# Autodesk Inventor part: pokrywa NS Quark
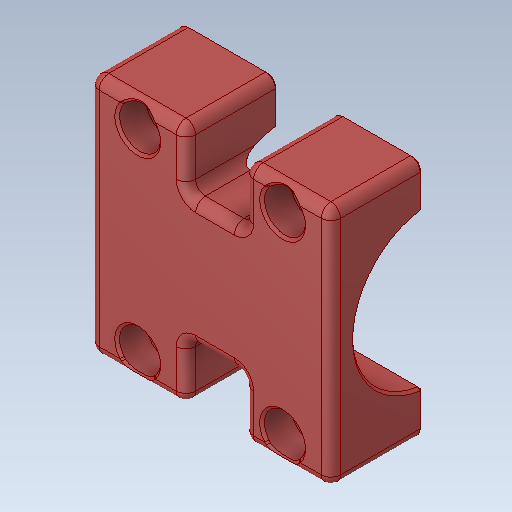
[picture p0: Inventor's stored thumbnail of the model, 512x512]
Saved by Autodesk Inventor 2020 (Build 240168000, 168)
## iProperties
Created: 2015-11
Part Number: pokrywa NS Quark
Material: Ogólny
Document SubType Name: Modeling
Designer: Tomasz
Density: 1 g/cm^3
Appearance: Domyślna
Sending System: SolidWorks 2017
Last Author: Tomasz
Last Saved: 2017-09-27
Author: Tomasz
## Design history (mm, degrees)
feature "Imported1"
node "Bryła1"
